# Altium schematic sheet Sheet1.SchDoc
size A4; SheetNumber: 1; SheetTotal: 1
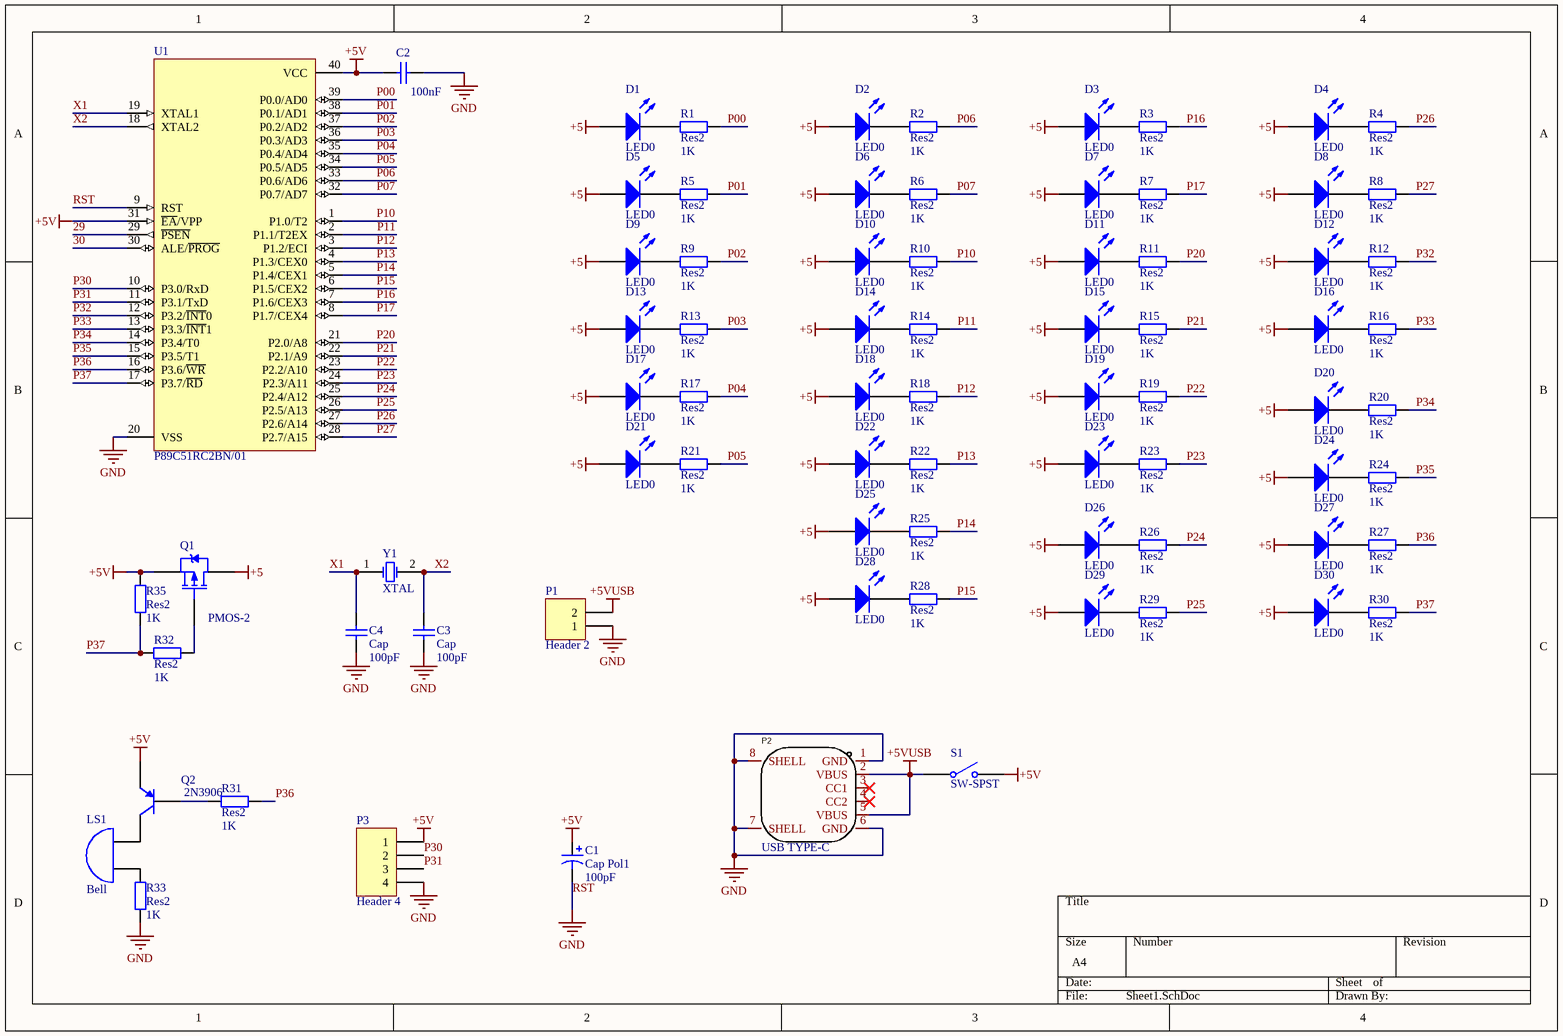
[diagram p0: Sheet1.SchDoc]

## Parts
C1  Cap Pol1  value 100pF  [RB7.6-15]
C2  value 100nF  [RAD-0.3]  (hidden comment: Cap)
C3  Cap  value 100pF  [RAD-0.3]
C4  Cap  value 100pF  [RAD-0.3]
D1  LED0  [LED-0]
D2  LED0  [LED-0]
D3  LED0  [LED-0]
D4  LED0  [LED-0]
D5  LED0  [LED-0]
D6  LED0  [LED-0]
D7  LED0  [LED-0]
D8  LED0  [LED-0]
D9  LED0  [LED-0]
D10  LED0  [LED-0]
D11  LED0  [LED-0]
D12  LED0  [LED-0]
D13  LED0  [LED-0]
D14  LED0  [LED-0]
D15  LED0  [LED-0]
D16  LED0  [LED-0]
D17  LED0  [LED-0]
D18  LED0  [LED-0]
D19  LED0  [LED-0]
D20  LED0  [LED-0]
D21  LED0  [LED-0]
D22  LED0  [LED-0]
D23  LED0  [LED-0]
D24  LED0  [LED-0]
D25  LED0  [LED-0]
D26  LED0  [LED-0]
D27  LED0  [LED-0]
D28  LED0  [LED-0]
D29  LED0  [LED-0]
D30  LED0  [LED-0]
LS1  Bell  [PIN2]
P1  Header 2  [HDR1X2]
P2  USB TYPE-C  [USB-C-SMD_TYPE-C-6PCB1.6-073]
P3  Header 4  [HDR1X4]
Q1  PMOS-2  [TO-220AB]
Q2  2N3906  [TO-92A]
R1  Res2  value 1K  [AXIAL-0.4]
R2  Res2  value 1K  [AXIAL-0.4]
R3  Res2  value 1K  [AXIAL-0.4]
R4  Res2  value 1K  [AXIAL-0.4]
R5  Res2  value 1K  [AXIAL-0.4]
R6  Res2  value 1K  [AXIAL-0.4]
R7  Res2  value 1K  [AXIAL-0.4]
R8  Res2  value 1K  [AXIAL-0.4]
R9  Res2  value 1K  [AXIAL-0.4]
R10  Res2  value 1K  [AXIAL-0.4]
R11  Res2  value 1K  [AXIAL-0.4]
R12  Res2  value 1K  [AXIAL-0.4]
R13  Res2  value 1K  [AXIAL-0.4]
R14  Res2  value 1K  [AXIAL-0.4]
R15  Res2  value 1K  [AXIAL-0.4]
R16  Res2  value 1K  [AXIAL-0.4]
R17  Res2  value 1K  [AXIAL-0.4]
R18  Res2  value 1K  [AXIAL-0.4]
R19  Res2  value 1K  [AXIAL-0.4]
R20  Res2  value 1K  [AXIAL-0.4]
R21  Res2  value 1K  [AXIAL-0.4]
R22  Res2  value 1K  [AXIAL-0.4]
R23  Res2  value 1K  [AXIAL-0.4]
R24  Res2  value 1K  [AXIAL-0.4]
R25  Res2  value 1K  [AXIAL-0.4]
R26  Res2  value 1K  [AXIAL-0.4]
R27  Res2  value 1K  [AXIAL-0.4]
R28  Res2  value 1K  [AXIAL-0.4]
R29  Res2  value 1K  [AXIAL-0.4]
R30  Res2  value 1K  [AXIAL-0.4]
R31  Res2  value 1K  [AXIAL-0.4]
R32  Res2  value 1K  [AXIAL-0.4]
R33  Res2  value 1K  [AXIAL-0.4]
R35  Res2  value 1K  [AXIAL-0.4]
S1  SW-SPST  [SPST-2]
U1  P89C51RC2BN/01  [SOT129-1]
Y1  XTAL  [R38]

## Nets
+5: D1.1(A) D2.1(A) D3.1(A) D4.1(A) D5.1(A) D6.1(A) D7.1(A) D8.1(A) D9.1(A) D10.1(A) D11.1(A) D12.1(A) D13.1(A) D14.1(A) D15.1(A) D16.1(A) D17.1(A) D18.1(A) D19.1(A) D20.1(A) D21.1(A) D22.1(A) D23.1(A) D24.1(A) D25.1(A) D26.1(A) D27.1(A) D28.1(A) D29.1(A) D30.1(A) Q1.2(D)
+5V: C1.1 C2.1 P3.1 Q1.3(S) Q2.1(E) R35.2 S1.2(NO) U1.31(~{EA}/VPP) U1.40(VCC)
+5VUSB: P1.2 P2.2(VBUS) P2.5(VBUS) S1.1(COMMON)
RST: C1.2 C2.2 C3.1 C4.1 P1.1 P2.1(GND) P2.6(GND) P2.7(SHELL) P2.8(SHELL) P3.4 R33.1 U1.9(RST) U1.20(VSS)  [also labelled GND]
29: U1.29(~{PSEN})
30: U1.30(ALE/~{PROG})
P00: R1.2 U1.39(P0.0/AD0)
P01: R5.2 U1.38(P0.1/AD1)
P02: R9.2 U1.37(P0.2/AD2)
P03: R13.2 U1.36(P0.3/AD3)
P04: R17.2 U1.35(P0.4/AD4)
P05: R21.2 U1.34(P0.5/AD5)
P06: R2.2 U1.33(P0.6/AD6)
P07: R6.2 U1.32(P0.7/AD7)
P10: R10.2 U1.1(P1.0/T2)
P11: R14.2 U1.2(P1.1/T2EX)
P12: R18.2 U1.3(P1.2/ECI)
P13: R22.2 U1.4(P1.3/CEX0)
P14: R25.2 U1.5(P1.4/CEX1)
P15: R28.2 U1.6(P1.5/CEX2)
P16: R3.2 U1.7(P1.6/CEX3)
P17: R7.2 U1.8(P1.7/CEX4)
P20: R11.2 U1.21(P2.0/A8)
P21: R15.2 U1.22(P2.1/A9)
P22: R19.2 U1.23(P2.2/A10)
P23: R23.2 U1.24(P2.3/A11)
P24: R26.2 U1.25(P2.4/A12)
P25: R29.2 U1.26(P2.5/A13)
P26: R4.2 U1.27(P2.6/A14)
P27: R8.2 U1.28(P2.7/A15)
P30: P3.2 U1.10(P3.0/RxD)
P31: P3.3 U1.11(P3.1/TxD)
P32: R12.2 U1.12(P3.2/~{INT}0)
P33: R16.2 U1.13(P3.3/~{INT}1)
P34: R20.2 U1.14(P3.4/T0)
P35: R24.2 U1.15(P3.5/T1)
P36: R27.2 R31.2 U1.16(P3.6/~{WR})
P37: R30.2 R32.2 R35.1 U1.17(P3.7/~{RD})
X1: C4.2 U1.19(XTAL1) Y1.1(OSC1)
X2: C3.2 U1.18(XTAL2) Y1.2(OSC2)
NetD1_2: D1.2(K) R1.1
NetD2_2: D2.2(K) R2.1
NetD3_2: D3.2(K) R3.1
NetD4_2: D4.2(K) R4.1
NetD5_2: D5.2(K) R5.1
NetD6_2: D6.2(K) R6.1
NetD7_2: D7.2(K) R7.1
NetD8_2: D8.2(K) R8.1
NetD9_2: D9.2(K) R9.1
NetD10_2: D10.2(K) R10.1
NetD11_2: D11.2(K) R11.1
NetD12_2: D12.2(K) R12.1
NetD13_2: D13.2(K) R13.1
NetD14_2: D14.2(K) R14.1
NetD15_2: D15.2(K) R15.1
NetD16_2: D16.2(K) R16.1
NetD17_2: D17.2(K) R17.1
NetD18_2: D18.2(K) R18.1
NetD19_2: D19.2(K) R19.1
NetD20_2: D20.2(K) R20.1
NetD21_2: D21.2(K) R21.1
NetD22_2: D22.2(K) R22.1
NetD23_2: D23.2(K) R23.1
NetD24_2: D24.2(K) R24.1
NetD25_2: D25.2(K) R25.1
NetD26_2: D26.2(K) R26.1
NetD27_2: D27.2(K) R27.1
NetD28_2: D28.2(K) R28.1
NetD29_2: D29.2(K) R29.1
NetD30_2: D30.2(K) R30.1
NetLS1_1: LS1.1(A) R33.2
NetLS1_2: LS1.2(B) Q2.3(C)
NetQ1_1: Q1.1(G) R32.1
NetQ2_2: Q2.2(B) R31.1

Not connected (* = marked no-connect by the designer): P2 3(CC1)* 4(CC2)*

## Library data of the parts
C1 = Cap Pol1: Polarized Capacitor (Radial)
C2-C4 = Cap: Capacitor
D1-D30 = LED0: Typical INFRARED GaAs LED
LS1 = Bell: Electrical Bell
P1 = Header 2: Header, 2-Pin
P2 = USB TYPE-C 6P: Symbol: TYPE-C 6P CB1.6(073); Add into BOM: yes; Number of Ports: 1; Number of Contacts: 6P; Current Rating - Power (Max): 5A
P3 = Header 4: Header, 4-Pin
Q1 = PMOS-2: P-Channel Power MOSFET; Note: Pin 4 not drawn and electrically connected to Pin 2.
Q2 = 2N3906: PNP General Purpose Amplifier
R1-R33 R35 = Res2: Resistor
S1 = SW-SPST: Single-Pole, Single-Throw Switch
U1 = P89C51RC2BN/01: 80C51 8-Bit Flash Microcontroller Family, 32 kB ISP/IAP Flash with 512 B RAM.
Y1 = XTAL: Crystal Oscillator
